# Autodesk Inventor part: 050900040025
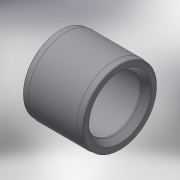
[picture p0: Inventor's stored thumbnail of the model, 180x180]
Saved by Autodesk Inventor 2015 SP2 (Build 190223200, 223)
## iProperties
Created: 2017-11
Part Number: 050900040025
Material: Generic
Description: PLASSON BUSHING-CEMENT PVC 40-25
Document SubType Name: Modeling
Designer: KIM
Density: 1 g/cm^3
Appearance: Default
Author: KIM
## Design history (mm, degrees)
derived "050900.ipt"
feature "Solid1::050900.ipt"
tag "TaggingFeature1"
body "Solid1"
other parameters: "d0" = 25, "d2" = 23, "d3" = 26, "d7" = 2.6, "d11" = 2.6, "d12" = 0.4, "d14" = 0.4, "d15" = 2.6, "d17" = 0.4, "d18" = 0.4, "d19" = 22.25, "d20" = 0.6, "d21" = 5.325, "d_" = 25, "L_" = 26, "l_" = 23, "z_" = 2
